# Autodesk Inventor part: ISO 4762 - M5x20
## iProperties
Author: Philippe
Created: 2001-12
Part Number: ISO 4762 - M5x20
Material: Par défaut
Catalog Web Link: file:///C:/Program Files/Autodesk/Inventor 5/Content/Iso/index.htm?doNavigateId=932883F9-F3A7-4770-8571-ED868C9DA26C|360AA416DD5A4F4880C34696ED28B4F3|true
Description: Vis cylindrique à six pans creux
Document SubType Name: Standard Catalog Part
Standard: ISO 4762 - M5x20
Designer: Philippe
CLASSIFICATION: 31161501 un/spsc
MANUFACTURER: ISO Système de normes
Control State: 0
Master: False
Checked Out: False
PropertySet Name: Design Tracking Control
Shininess: 20.0
Angle Display Precision: 2
Document Length Units: 11269
Document Angle Units: 11283
Document Time Units: 11279
Document Mass Units: 11290
Document Length Units Precision: 3
Document Angle Units Precision: 2
Compacted: False
PropertySet Name: _Private Model Information
Density: 0.0
Volumn: 0.0
Area: 0.0
PropertySet Name: Model Information
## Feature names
1. Base1
